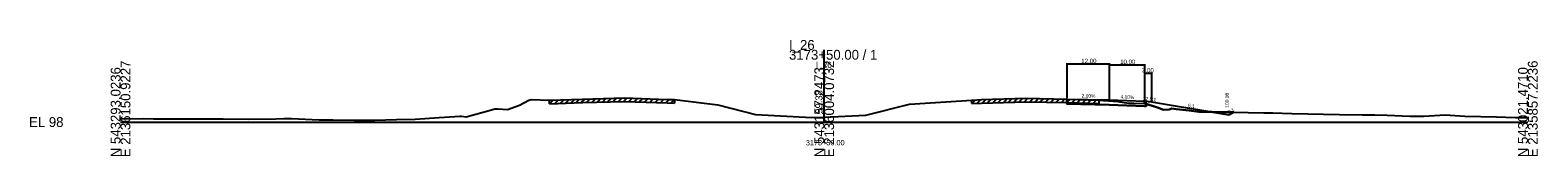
# Model space of a CAD drawing. Extents: x -13101 to 4803, y -924 to 22390.
# Drawn here: x -25.7 to 402.8, y 19490.3 to 19523.4 of the extents above; entities that cross this region are included whole.
import ezdxf

# ---------------------------------------------------------------- set-up
doc = ezdxf.new("R2010")
doc.units = 0
for name, color, linetype in [('RD_GPK_XS_Cell', 7, 'Continuous'), ('RD_XD_TX_Width', 7, 'Continuous'), ('RD_XS_Base', 7, 'Continuous'), ('RD_XS_EarthShd', 7, 'Continuous'), ('RD_XS_EwShp', 7, 'Continuous'), ('RD_XS_ExGround', 7, 'Continuous'), ('RD_XS_ExPaveRet', 7, 'Continuous'), ('RD_XS_OSBase', 7, 'Continuous'), ('RD_XS_Pave', 7, 'Continuous'), ('RD_XS_TieSlope', 7, 'Continuous'), ('RD_XS_TX_Baseline', 7, 'Continuous'), ('RD_XS_TX_Elev_EX', 7, 'Continuous'), ('RD_XS_TX_Elev_PR', 7, 'Continuous'), ('RD_XS_TX_ShdSlope', 7, 'Continuous'), ('RD_XS_TX_Slope', 7, 'Continuous'), ('RD_XS_TX_Station', 7, 'Continuous')]:
    doc.layers.add(name, color=color, linetype=linetype)

msp = doc.modelspace()

# ---------------------------------------------------------------- linework, layer by layer
at = {"layer": 'RD_GPK_XS_Cell'}
for p, q in [((200, 19500), (200, 19520.52)), ((0, 19500), (200, 19500)), ((200, 19500), (400, 19500))]:
    msp.add_line(p, q, dxfattribs=at)
at = {"layer": 'RD_XD_TX_Width'}
for p, q in [((269, 19516.7), (269, 19506.75)), ((269, 19516.5), (281, 19516.5)), ((281, 19516.7), (281, 19506.51)), ((281, 19516.46), (281, 19506.51)), ((281, 19516.26), (291, 19516.26)), ((291, 19516.46), (291, 19506.11)), ((291, 19514.06), (291, 19506.11)), ((291, 19513.86), (293, 19513.86)), ((293, 19514.06), (293, 19505.95))]:
    msp.add_line(p, q, dxfattribs=at)
at = {"layer": 'RD_XS_Base'}
for p, q in [((269, 19505.15), (281, 19504.91)), ((281, 19504.91), (291, 19504.51))]:
    msp.add_line(p, q, dxfattribs=at)
at = {"layer": 'RD_XS_EarthShd'}
msp.add_line((291, 19505.91), (293, 19505.75), dxfattribs=at)
at = {"layer": 'RD_XS_EwShp'}
for points in [[(283.46, 19505.85), (286.46, 19505.36), (287.99, 19505.34), (291.08, 19505.31), (291.5, 19505.17), (291.5, 19504.49), (291, 19504.51), (281, 19504.91), (269, 19505.15), (269, 19506.15), (269, 19506.55), (269.08, 19506.55), (278.02, 19506.25)], [(293, 19505.75), (310.2, 19502.88), (306.46, 19502.94), (303.76, 19503.32), (300.04, 19503.67), (298.83, 19503.89), (298.03, 19503.56), (296.46, 19503.51), (294.69, 19504.1), (291.5, 19505.17), (291.5, 19505.49), (291, 19505.51), (291, 19505.91)], [(315, 19502.08), (316.41, 19502.79), (310.2, 19502.88)]]:
    msp.add_lwpolyline(points, close=True, dxfattribs=at)
at = {"layer": 'RD_XS_ExGround'}
msp.add_lwpolyline([(0, 19500.88), (6.4, 19500.99), (9.4, 19500.95), (16.4, 19500.9), (23.5, 19500.92), (26.4, 19500.95), (29.2, 19500.89), (36.41, 19500.82), (44.09, 19500.94), (46.41, 19501.03), (48.56, 19500.99), (56.41, 19500.67), (60.44, 19500.65), (66.41, 19500.53), (72.3, 19500.58), (78.39, 19500.74), (83.72, 19500.83), (90.57, 19501.28), (95, 19501.58), (96.42, 19501.71), (96.9, 19501.66), (98.27, 19501.46), (105.4, 19503.43), (106.42, 19503.76), (107.21, 19503.72), (110, 19503.61), (113.39, 19504.81), (116.09, 19506.21), (116.69, 19506.37), (121.94, 19506.19), (131.26, 19506.52), (143.28, 19506.84), (155.36, 19506.44), (157.46, 19506.37), (169.72, 19504.93), (180.5, 19502.1), (196.47, 19501.25), (200, 19501.38), (211.84, 19501.95), (224.28, 19505.08), (241.93, 19506.24), (244.7, 19506.4), (257.27, 19506.78), (269.08, 19506.55), (278.02, 19506.25), (283.46, 19505.85), (286.46, 19505.36), (287.99, 19505.34), (291.08, 19505.31), (294.69, 19504.1), (296.46, 19503.51), (298.03, 19503.56), (298.83, 19503.89), (300.04, 19503.67), (303.76, 19503.32), (306.46, 19502.94), (320.53, 19502.72), (324.99, 19502.63), (326.46, 19502.63), (327.48, 19502.61), (332.9, 19502.46), (346.47, 19502.13), (353.04, 19502.08), (356.47, 19502.07), (360.04, 19501.95), (366.47, 19501.7), (370.47, 19501.7), (376.47, 19502.02), (382.1, 19501.68), (391.1, 19501.53), (396.48, 19501.33), (400, 19501.28)], dxfattribs=at)
at = {"layer": 'RD_XS_ExPaveRet'}
for p, q in [((141.44, 19505.79), (142.47, 19506.82)), ((142.94, 19505.83), (143.93, 19506.82)), ((121.94, 19505.19), (122.98, 19506.23)), ((121.94, 19505.19), (121.94, 19506.19)), ((121.94, 19505.19), (131.26, 19505.52)), ((123.44, 19505.24), (124.48, 19506.28)), ((124.94, 19505.3), (125.98, 19506.33)), ((126.44, 19505.35), (127.48, 19506.39)), ((127.94, 19505.4), (128.98, 19506.44)), ((129.44, 19505.46), (130.48, 19506.5)), ((130.94, 19505.51), (131.97, 19506.54)), ((131.26, 19505.52), (143.28, 19505.84)), ((132.44, 19505.55), (133.47, 19506.58)), ((133.94, 19505.59), (134.97, 19506.62)), ((135.44, 19505.63), (136.47, 19506.66)), ((136.94, 19505.67), (137.97, 19506.7)), ((138.44, 19505.71), (139.47, 19506.74)), ((139.94, 19505.75), (140.97, 19506.78)), ((143.28, 19505.84), (155.36, 19505.44)), ((144.44, 19505.8), (145.41, 19506.77)), ((145.94, 19505.75), (146.91, 19506.72)), ((147.44, 19505.7), (148.41, 19506.67)), ((148.94, 19505.65), (149.91, 19506.62)), ((150.44, 19505.6), (151.41, 19506.57)), ((151.94, 19505.55), (152.91, 19506.52)), ((153.44, 19505.5), (154.41, 19506.47)), ((154.94, 19505.45), (155.91, 19506.42)), ((155.36, 19505.44), (157.46, 19505.37)), ((156.44, 19505.4), (157.41, 19506.37)), ((157.46, 19506.37), (157.46, 19505.37)), ((241.93, 19505.24), (242.99, 19506.3)), ((241.93, 19505.24), (241.93, 19506.24)), ((241.93, 19505.24), (244.7, 19505.4)), ((243.43, 19505.33), (244.49, 19506.39)), ((244.7, 19505.4), (257.27, 19505.78)), ((244.93, 19505.41), (245.96, 19506.44)), ((246.43, 19505.46), (247.46, 19506.49)), ((247.93, 19505.5), (248.96, 19506.53)), ((249.43, 19505.54), (250.46, 19506.58)), ((250.93, 19505.59), (251.96, 19506.62)), ((252.43, 19505.63), (253.46, 19506.66)), ((253.93, 19505.68), (254.96, 19506.71)), ((255.43, 19505.72), (256.46, 19506.75)), ((256.93, 19505.77), (257.92, 19506.77)), ((257.27, 19505.78), (269.08, 19505.55)), ((258.43, 19505.76), (259.41, 19506.74)), ((259.93, 19505.73), (260.91, 19506.71)), ((261.43, 19505.7), (262.41, 19506.68)), ((262.93, 19505.67), (263.91, 19506.65)), ((264.43, 19505.64), (265.41, 19506.62)), ((265.93, 19505.61), (266.91, 19506.59)), ((267.43, 19505.58), (268.41, 19506.56)), ((268.93, 19505.55), (269.9, 19506.52)), ((269.08, 19505.55), (278.02, 19505.25)), ((270.43, 19505.5), (271.39, 19506.47)), ((271.93, 19505.45), (272.89, 19506.42)), ((273.43, 19505.4), (274.39, 19506.37)), ((274.93, 19505.35), (275.89, 19506.32)), ((276.43, 19505.3), (277.39, 19506.27)), ((278.02, 19506.25), (278.02, 19505.25))]:
    msp.add_line(p, q, dxfattribs=at)
at = {"layer": 'RD_XS_OSBase'}
for p, q in [((269, 19506.15), (269, 19506.55)), ((269, 19505.15), (269, 19506.15)), ((291, 19505.51), (291, 19505.91)), ((291.5, 19505.49), (291, 19505.51)), ((291, 19504.51), (291.5, 19504.49)), ((291.5, 19504.49), (291.5, 19505.49))]:
    msp.add_line(p, q, dxfattribs=at)
at = {"layer": 'RD_XS_Pave'}
for p, q in [((269, 19506.55), (281, 19506.31)), ((281, 19506.31), (291, 19505.91))]:
    msp.add_line(p, q, dxfattribs=at)
at = {"layer": 'RD_XS_TieSlope'}
for p, q in [((293, 19505.75), (315, 19502.08)), ((315, 19502.08), (316.41, 19502.79))]:
    msp.add_line(p, q, dxfattribs=at)

# ---------------------------------------------------------------- texts
at = {"layer": 'RD_GPK_XS_Cell'}
for s, p in [('3173+50.00 / 1', (190, 19517.72)), ('I_26', (190, 19520.52)), ('EL 98', (-26, 19498.6))]:
    msp.add_text(s, height=2.8, dxfattribs=at).set_placement(p)
for s, p in [('N 543293.0236', (0, 19490)), ('E 2136150.9227', (2.8, 19490)), ('N 543157.2473', (200, 19490)), ('E 2136004.0732', (202.8, 19490)), ('N 543021.4710', (400, 19490)), ('E 2135857.2236', (402.8, 19490))]:
    msp.add_text(s, height=2.8, rotation=90, dxfattribs=at).set_placement(p)
at = {"layer": 'RD_XD_TX_Width'}
for s, p in [('12.00', (273.07, 19516.75)), ('10.00', (284.11, 19516.51)), ('2.00', (290.31, 19514.11))]:
    msp.add_text(s, height=1.25, dxfattribs=at).set_placement(p)
at = {"layer": 'RD_XS_TX_Baseline'}
msp.add_text('I_26', height=1.75, dxfattribs=at).set_placement((197.6, 19515.38))
at = {"layer": 'RD_XS_TX_Elev_EX'}
msp.add_text('99.38', height=2, rotation=90, dxfattribs=at).set_placement((199.5, 19502.38))
at = {"layer": 'RD_XS_TX_Elev_PR'}
msp.add_text('100.08', height=1, rotation=90, dxfattribs=at).set_placement((315, 19504.08))
at = {"layer": 'RD_XS_TX_ShdSlope'}
msp.add_text('12.5:1', height=1, rotation=355.4261, dxfattribs=at).set_placement((290.51, 19506.2))
msp.add_text('12.5:1', height=1, rotation=355.4261, dxfattribs=at).set_placement((290.51, 19506.2))
at = {"layer": 'RD_XS_TX_Slope'}
for s, rotation, p in [('2.00%', 358.8542, (273.16, 19506.97)), ('4.00%', 357.7094, (284.22, 19506.68)), ('6:1', 350.5377, (303.35, 19504.28)), ('2:1', 26.5651, (314.92, 19502.32))]:
    msp.add_text(s, height=1, rotation=rotation, dxfattribs=at).set_placement(p)
at = {"layer": 'RD_XS_TX_Station'}
msp.add_text('3173+50.00', height=1.5, dxfattribs=at).set_placement((194.79, 19493.38))

doc.saveas('drawing.dxf')
